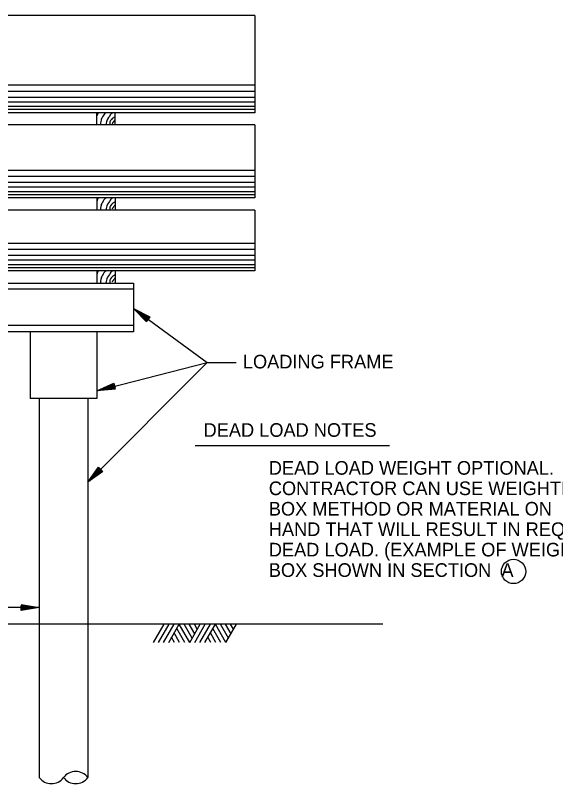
# Model space of a CAD drawing. Extents: x 22378.6 to 22422.6, y 22377.7 to 22411.7.
# Drawn here: x 22393.16 to 22398.72, y 22384.1 to 22392 of the extents above; entities that cross this region are included whole.
import ezdxf

# ---------------------------------------------------------------- set-up
doc = ezdxf.new("R2010")
doc.units = 0
for name, color, linetype in [('Level 1', 7, 'Continuous'), ('Level 2', 7, 'Continuous'), ('Level 4', 7, 'Continuous'), ('Level 7', 7, 'Continuous')]:
    doc.layers.add(name, color=color, linetype=linetype)

msp = doc.modelspace()

# ---------------------------------------------------------------- linework, layer by layer
at = {"layer": 'Level 1'}
for p, q in [((22395.6253, 22391.0607), (22389.3753, 22391.0607)), ((22395.6253, 22391.0295), (22389.3753, 22391.0295)), ((22395.6253, 22390.1857), (22389.3753, 22390.1857)), ((22395.6253, 22390.1545), (22389.3753, 22390.1545)), ((22395.6253, 22389.4357), (22389.3753, 22389.4357)), ((22395.6253, 22389.4045), (22389.3753, 22389.4045)), ((22394.3753, 22388.9855), (22394.3753, 22388.9855)), ((22394.4173, 22388.9548), (22394.4173, 22388.9548)), ((22394.0003, 22388.1416), (22394.0003, 22388.1416)), ((22394.0507, 22388.1544), (22394.0507, 22388.1544)), ((22393.9433, 22387.2373), (22393.9433, 22387.2373)), ((22393.9065, 22387.2005), (22393.9065, 22387.2005)), ((22393.4065, 22385.9134), (22391.5471, 22385.9134)), ((22393.3545, 22385.9134), (22393.3545, 22385.9134)), ((22393.4065, 22385.9134), (22393.4065, 22385.9134)), ((22394.582, 22385.5556), (22394.6902, 22385.7431)), ((22394.634, 22385.5556), (22394.7422, 22385.7431)), ((22394.686, 22385.5556), (22394.7942, 22385.7431)), ((22394.7379, 22385.5556), (22394.8461, 22385.7431)), ((22394.9544, 22385.5556), (22394.8461, 22385.7431)), ((22394.9804, 22385.6006), (22394.8981, 22385.7431)), ((22395.0064, 22385.6456), (22394.9501, 22385.7431)), ((22394.9544, 22385.5556), (22395.0626, 22385.743)), ((22395.0324, 22385.6906), (22395.0021, 22385.7431)), ((22395.0064, 22385.5556), (22395.1147, 22385.7431)), ((22395.0582, 22385.5556), (22395.1666, 22385.7431)), ((22395.1102, 22385.5556), (22395.2186, 22385.7431)), ((22395.3269, 22385.5556), (22395.2186, 22385.7431)), ((22395.3529, 22385.6006), (22395.2706, 22385.7431)), ((22395.3789, 22385.6456), (22395.3226, 22385.7431)), ((22395.3269, 22385.5556), (22395.4352, 22385.7431)), ((22395.4049, 22385.6906), (22395.3746, 22385.7431)), ((22394.8504, 22385.5556), (22394.7941, 22385.6531)), ((22394.9024, 22385.5556), (22394.8201, 22385.6981)), ((22395.2229, 22385.5556), (22395.1666, 22385.6531)), ((22395.2749, 22385.5556), (22395.1926, 22385.6981)), ((22394.7985, 22385.5556), (22394.7682, 22385.6081)), ((22395.171, 22385.5556), (22395.1407, 22385.6081))]:
    msp.add_line(p, q, dxfattribs=at)
for points in [[(22394.0132, 22390.9978), (22394.0069, 22390.9875), (22394.0007, 22390.9679)], [(22394.0919, 22390.9964), (22394.0799, 22390.9885), (22394.0701, 22390.9767), (22394.0633, 22390.9658), (22394.0563, 22390.9548), (22394.0486, 22390.9417), (22394.0448, 22390.9305), (22394.0416, 22390.9203), (22394.0402, 22390.9077), (22394.0355, 22390.8933), (22394.0348, 22390.881), (22394.0351, 22390.8741)], [(22394.16, 22390.9946), (22394.151, 22390.9913), (22394.1437, 22390.9834), (22394.1361, 22390.9746), (22394.1277, 22390.96), (22394.1188, 22390.9484), (22394.1088, 22390.9328), (22394.1021, 22390.916), (22394.0987, 22390.9039), (22394.0947, 22390.89), (22394.0928, 22390.8723)], [(22394.1856, 22390.9564), (22394.1753, 22390.9502), (22394.1647, 22390.9434), (22394.1578, 22390.9375), (22394.1481, 22390.9286), (22394.1396, 22390.9177), (22394.134, 22390.9038), (22394.1314, 22390.8898), (22394.1309, 22390.878)], [(22394.1865, 22390.9244), (22394.181, 22390.9207), (22394.1766, 22390.9136), (22394.1718, 22390.9063), (22394.1688, 22390.9018), (22394.1611, 22390.8927), (22394.1567, 22390.8809)], [(22394.0132, 22390.1228), (22394.0069, 22390.1125), (22394.0007, 22390.0929)], [(22394.0919, 22390.1214), (22394.0799, 22390.1136), (22394.0701, 22390.1017), (22394.0633, 22390.0908), (22394.0563, 22390.0798), (22394.0486, 22390.0667), (22394.0448, 22390.0555), (22394.0416, 22390.0453), (22394.0402, 22390.0328), (22394.0355, 22390.0183), (22394.0348, 22390.006), (22394.0351, 22389.9992)], [(22394.16, 22390.1197), (22394.151, 22390.1164), (22394.1437, 22390.1085), (22394.1361, 22390.0996), (22394.1277, 22390.085), (22394.1188, 22390.0735), (22394.1088, 22390.0578), (22394.1021, 22390.041), (22394.0987, 22390.0289), (22394.0947, 22390.0151), (22394.0928, 22389.9973)], [(22394.1856, 22390.0814), (22394.1753, 22390.0753), (22394.1647, 22390.0684), (22394.1578, 22390.0625), (22394.1481, 22390.0536), (22394.1396, 22390.0427), (22394.134, 22390.0288), (22394.1314, 22390.0149), (22394.1309, 22390.003)], [(22394.1865, 22390.0494), (22394.181, 22390.0458), (22394.1766, 22390.0387), (22394.1718, 22390.0313), (22394.1688, 22390.0269), (22394.1611, 22390.0177), (22394.1567, 22390.0059)], [(22394.0132, 22389.3728), (22394.0069, 22389.3625), (22394.0007, 22389.3429)], [(22394.0919, 22389.3714), (22394.0799, 22389.3636), (22394.0701, 22389.3517), (22394.0633, 22389.3408), (22394.0563, 22389.3298), (22394.0486, 22389.3167), (22394.0448, 22389.3055), (22394.0416, 22389.2953), (22394.0402, 22389.2828), (22394.0355, 22389.2683), (22394.0348, 22389.256), (22394.0351, 22389.2492)], [(22394.16, 22389.3697), (22394.151, 22389.3664), (22394.1437, 22389.3585), (22394.1361, 22389.3496), (22394.1277, 22389.335), (22394.1188, 22389.3235), (22394.1088, 22389.3078), (22394.1021, 22389.291), (22394.0987, 22389.2789), (22394.0947, 22389.2651), (22394.0928, 22389.2473)], [(22394.1856, 22389.3314), (22394.1753, 22389.3253), (22394.1647, 22389.3184), (22394.1578, 22389.3125), (22394.1481, 22389.3036), (22394.1396, 22389.2927), (22394.134, 22389.2788), (22394.1314, 22389.2649), (22394.1309, 22389.253)], [(22394.1865, 22389.2994), (22394.181, 22389.2958), (22394.1766, 22389.2887), (22394.1718, 22389.2813), (22394.1688, 22389.2769), (22394.1611, 22389.2677), (22394.1567, 22389.2559)], [(22394.3753, 22388.9855), (22395.1339, 22388.43), (22395.4302, 22388.43)], [(22394.5079, 22388.85), (22394.3753, 22388.9855), (22394.5445, 22388.9001), (22394.5132, 22388.8573), (22394.4173, 22388.9548), (22394.5322, 22388.8967), (22394.5121, 22388.8693), (22394.4576, 22388.9253), (22394.5198, 22388.8934), (22394.5115, 22388.8821), (22394.4996, 22388.8945)], [(22393.9065, 22387.2005), (22395.1339, 22388.43), (22395.4302, 22388.43)], [(22394.0003, 22388.1416), (22395.133, 22388.4314), (22395.4294, 22388.4314)], [(22394.1892, 22388.1579), (22394.0003, 22388.1416), (22394.1738, 22388.2179), (22394.187, 22388.1666), (22394.0507, 22388.1544), (22394.1686, 22388.2063), (22394.177, 22388.1733), (22394.0992, 22388.1668), (22394.1633, 22388.1946), (22394.1667, 22388.181), (22394.1495, 22388.1797)], [(22394.0606, 22387.3109), (22393.9065, 22387.2005), (22394.0167, 22387.3547), (22394.0542, 22387.3173), (22393.9433, 22387.2373), (22394.0181, 22387.342), (22394.0422, 22387.318), (22393.9786, 22387.2727), (22394.0196, 22387.3293), (22394.0295, 22387.3194), (22394.0153, 22387.3095)], [(22393.2195, 22385.9444), (22393.4065, 22385.9134), (22393.2195, 22385.8824), (22393.2195, 22385.9354), (22393.3545, 22385.9134), (22393.2275, 22385.8924), (22393.2275, 22385.9264), (22393.3045, 22385.9134), (22393.2355, 22385.9024), (22393.2355, 22385.9164), (22393.2525, 22385.9134)]]:
    msp.add_lwpolyline(points, dxfattribs=at)
at = {"layer": 'Level 2'}
for p, q in [((22395.6253, 22391.2795), (22389.3753, 22391.2795)), ((22395.6253, 22391.217), (22389.3753, 22391.217)), ((22395.6253, 22391.1545), (22389.3753, 22391.1545)), ((22395.6253, 22391.1076), (22389.3753, 22391.1076)), ((22394.0003, 22390.8732), (22394.0003, 22390.9982)), ((22394.1878, 22390.8732), (22394.1878, 22390.9982)), ((22395.6253, 22390.4045), (22389.3753, 22390.4045)), ((22395.6253, 22390.342), (22389.3753, 22390.342)), ((22395.6253, 22390.2795), (22389.3753, 22390.2795)), ((22395.6253, 22390.2326), (22389.3753, 22390.2326)), ((22394.0003, 22390.1232), (22394.0003, 22389.9982)), ((22394.1878, 22390.1232), (22394.1878, 22389.9982)), ((22395.6253, 22389.6545), (22389.3753, 22389.6545)), ((22395.6253, 22389.592), (22389.3753, 22389.592)), ((22395.6253, 22389.5295), (22389.3753, 22389.5295)), ((22395.6253, 22389.4826), (22389.3753, 22389.4826)), ((22394.0003, 22389.3732), (22394.0003, 22389.2482)), ((22394.1878, 22389.3732), (22394.1878, 22389.2482)), ((22394.3753, 22389.1857), (22389.3753, 22389.1857)), ((22394.3753, 22388.8107), (22389.3753, 22388.8107)), ((22389.3753, 22385.7482), (22396.9404, 22385.7482)), ((22393.4065, 22385.7482), (22393.4065, 22384.1673)), ((22393.9065, 22385.7482), (22393.9065, 22384.1673))]:
    msp.add_line(p, q, dxfattribs=at)
for centre, radius, start, end in [((22393.7812, 22384.0737), 0.156, 36.84504, 143.15496), ((22393.5314, 22384.261), 0.1561, 216.87181, 323.12819), ((22393.7812, 22384.2611), 0.1561, 216.90623, 323.09376)]:
    msp.add_arc(centre, radius, start, end, dxfattribs=at)
at = {"layer": 'Level 7'}
for p, q in [((22395.6253, 22391.9982), (22389.3753, 22391.9982)), ((22395.6253, 22391.9982), (22395.6253, 22390.9982)), ((22395.6253, 22390.9982), (22389.3753, 22390.9982)), ((22395.6253, 22390.8732), (22389.3753, 22390.8732)), ((22395.6253, 22390.8732), (22395.6253, 22390.1232)), ((22395.6253, 22390.1232), (22389.3753, 22390.1232)), ((22395.6253, 22389.9982), (22389.3753, 22389.9982)), ((22395.6253, 22389.9982), (22395.6253, 22389.3732)), ((22395.6253, 22389.3732), (22389.3753, 22389.3732)), ((22389.3753, 22389.2482), (22394.3753, 22389.2482)), ((22394.3753, 22389.2482), (22394.3753, 22388.7482)), ((22394.3753, 22388.7482), (22389.3753, 22388.7482)), ((22393.3128, 22388.7482), (22393.3128, 22388.0607)), ((22394.0003, 22388.7482), (22394.0003, 22388.0607)), ((22394.0003, 22388.0607), (22393.3128, 22388.0607)), ((22393.4065, 22388.0607), (22393.4065, 22385.7482)), ((22393.9065, 22388.0607), (22393.9065, 22385.7482)), ((22395.0099, 22387.5789), (22397.0091, 22387.5789))]:
    msp.add_line(p, q, dxfattribs=at)
msp.add_circle((22398.2848, 22386.2848), 0.125, dxfattribs=at)

# ---------------------------------------------------------------- texts
at = {"layer": 'Level 4'}
for s, p in [('LOADING FRAME', (22395.5007, 22388.3707)), ('DEAD LOAD NOTES', (22395.0966, 22387.6682)), ('DEAD LOAD WEIGHT OPTIONAL.', (22395.7676, 22387.279)), ('CONTRACTOR CAN USE WEIGHTED', (22395.7676, 22387.069)), ('BOX METHOD OR MATERIAL ON', (22395.7676, 22386.859)), ('HAND THAT WILL RESULT IN REQUIRED', (22395.7676, 22386.649)), ('DEAD LOAD. (EXAMPLE OF WEIGHTED', (22395.7676, 22386.439)), ('BOX SHOWN IN SECTION  A', (22395.7676, 22386.229))]:
    msp.add_text(s, height=0.14, dxfattribs=at).set_placement(p)

doc.saveas('drawing.dxf')
